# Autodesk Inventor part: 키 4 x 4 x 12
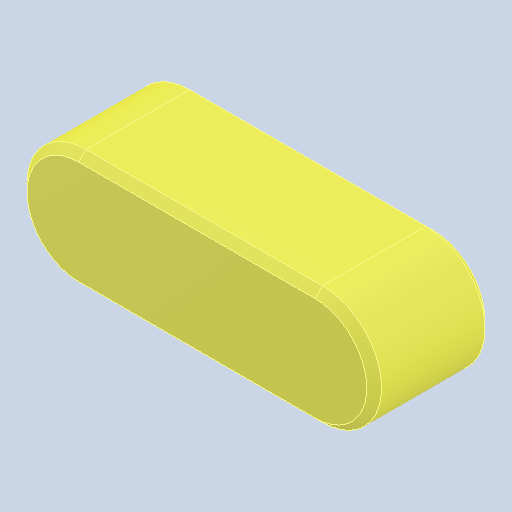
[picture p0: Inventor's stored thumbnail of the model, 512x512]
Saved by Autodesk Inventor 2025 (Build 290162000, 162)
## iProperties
Created: 2024-07
Part Number: 키 4 x 4 x 12
Material: 강철, 연강
Description: 키 및 해당 키홈
Document SubType Name: Modeling
Designer: parkm
Density: 7.85 g/cm^3
Appearance: 기본값
Author: jhkim
Sending System: Autodesk Inventor 2025
Preprocessor: ST-DEVELOPER v20
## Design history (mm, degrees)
feature "Solid1"
node "솔리드1"
